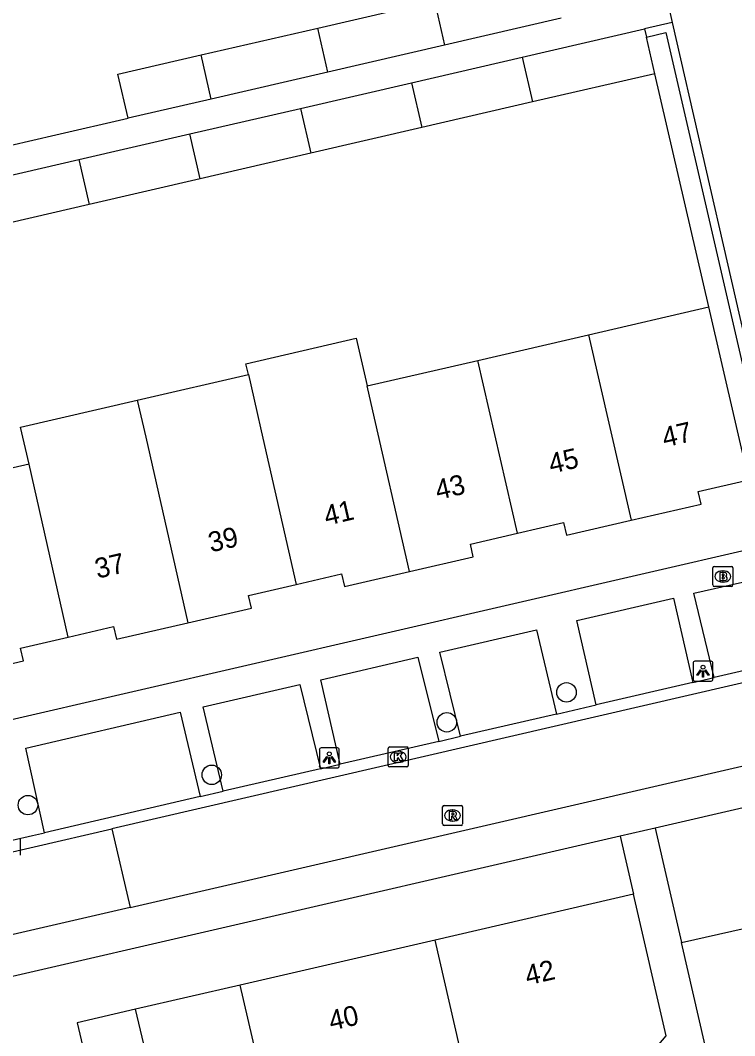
# Model space of a CAD drawing. Extents: x 156414 to 157775, y 382335 to 383765.
# Drawn here: x 156849.7 to 156885.5, y 382647.1 to 382698 of the extents above; entities that cross this region are included whole.
import ezdxf

# ---------------------------------------------------------------- set-up
doc = ezdxf.new("R2010")
doc.units = 0
for name, color, linetype in [('IMGEO_Boom', 7, 'Continuous'), ('IMGEO_Brandkraan', 7, 'Continuous'), ('IMGEO_Groenvoorziening', 7, 'Continuous'), ('IMGEO_Kolk', 7, 'Continuous'), ('IMGEO_Lichtpunt', 7, 'Continuous'), ('IMGEO_Muur', 7, 'Continuous'), ('IMGEO_Pand', 7, 'Continuous'), ('IMGEO_Pand_nummerreeks', 7, 'Continuous'), ('IMGEO_Rijbaan_lokaal_gesloten', 7, 'Continuous'), ('IMGEO_Rijbaan_lokaal_open', 7, 'Continuous'), ('IMGEO_Rioolput', 7, 'Continuous'), ('IMGEO_Voetpad_open', 7, 'Continuous')]:
    doc.layers.add(name, color=color, linetype=linetype)

msp = doc.modelspace()

# ---------------------------------------------------------------- linework, layer by layer
at = {"layer": 'IMGEO_Boom'}
for centre in [(156877.04, 382664.328), (156871.045, 382662.829), (156859.265, 382660.195), (156850.052, 382658.68)]:
    msp.add_circle(centre, 0.489, dxfattribs=at)
at = {"layer": 'IMGEO_Brandkraan'}
for p, q in [((156884.376, 382669.709), (156884.376, 382670.561)), ((156884.451, 382670.635), (156885.303, 382670.635)), ((156884.864, 382670.415), (156884.889, 382670.415)), ((156885.377, 382670.561), (156885.377, 382669.709)), ((156885.303, 382669.635), (156884.451, 382669.635)), ((156884.887, 382669.855), (156884.862, 382669.855))]:
    msp.add_line(p, q, dxfattribs=at)
for points in [[(156884.376, 382669.709), (156884.376, 382670.561)], [(156884.451, 382670.635), (156885.303, 382670.635)], [(156885.377, 382670.561), (156885.377, 382669.709)], [(156884.724, 382670.335), (156884.724, 382669.935), (156884.937, 382669.935)], [(156884.955, 382670.335), (156884.724, 382670.335)], [(156884.903, 382670.254), (156884.849, 382670.254), (156884.849, 382670.178)], [(156884.849, 382670.178), (156884.902, 382670.178)], [(156884.911, 382670.102), (156884.849, 382670.102), (156884.849, 382670.021)], [(156884.849, 382670.021), (156884.911, 382670.021)], [(156885.303, 382669.635), (156884.451, 382669.635)]]:
    msp.add_lwpolyline(points, dxfattribs=at)
for centre, radius, start, end in [((156884.453, 382670.559), 0.0765, 91.552, 178.448), ((156884.453, 382670.559), 0.0765, 91.552, 178.448), ((156885.301, 382670.559), 0.0765, 1.552, 88.448), ((156885.301, 382670.559), 0.0765, 1.552, 88.448), ((156884.904, 382670.216), 0.0379, 267.8285, 90.9355), ((156884.912, 382670.061), 0.0404, 269.8759, 90.5077), ((156884.943, 382670.186), 0.251, 268.6676, 293.5347), ((156884.959, 382670.19), 0.145, 59.4692, 91.5367), ((156884.984, 382670.237), 0.0922, 285.5137, 58.1501), ((156884.989, 382670.045), 0.105, 301.3115, 78.989), ((156884.453, 382669.711), 0.0765, 181.552, 268.448), ((156884.453, 382669.711), 0.0765, 181.552, 268.448), ((156885.301, 382669.711), 0.0765, 271.552, 358.448), ((156885.301, 382669.711), 0.0765, 271.552, 358.448)]:
    msp.add_arc(centre, radius, start, end, dxfattribs=at)
for centre, major_axis, ratio, start_param, end_param in [((156884.863, 382670.135), (-0.387, 0.002), 0.722429, 4.712389, 7.853982), ((156884.888, 382670.135), (-0.39, 0.002), 0.717154, 1.570796, 4.712389)]:
    msp.add_ellipse(centre, major_axis=major_axis, ratio=ratio, start_param=start_param, end_param=end_param, dxfattribs=at)
at = {"layer": 'IMGEO_Groenvoorziening'}
msp.add_lwpolyline([(156884.178, 382683.642), (156881.475, 382695.326)], dxfattribs=at)
at = {"layer": 'IMGEO_Kolk'}
for p, q in [((156868.106, 382660.67), (156868.106, 382661.522)), ((156868.181, 382661.596), (156869.033, 382661.596)), ((156868.594, 382661.376), (156868.619, 382661.376)), ((156869.107, 382661.522), (156869.107, 382660.67)), ((156868.617, 382660.816), (156868.592, 382660.816)), ((156869.033, 382660.596), (156868.181, 382660.596)), ((156849.67, 382657.017), (156849.67, 382656.165))]:
    msp.add_line(p, q, dxfattribs=at)
for points in [[(156868.106, 382660.67), (156868.106, 382661.522)], [(156868.181, 382661.596), (156869.033, 382661.596)], [(156868.427, 382661.296), (156868.55, 382661.296), (156868.55, 382661.145), (156868.68, 382661.296), (156868.844, 382661.296), (156868.698, 382661.145), (156868.851, 382660.896), (156868.699, 382660.896), (156868.614, 382661.06), (156868.55, 382660.993), (156868.55, 382660.896), (156868.427, 382660.896), (156868.427, 382661.296)], [(156869.107, 382661.522), (156869.107, 382660.67)], [(156869.033, 382660.596), (156868.181, 382660.596)], [(156849.67, 382657.017), (156849.67, 382656.165)]]:
    msp.add_lwpolyline(points, dxfattribs=at)
for centre, start, end in [((156868.183, 382661.52), 91.552, 178.448), ((156868.183, 382661.52), 91.552, 178.448), ((156869.031, 382661.52), 1.552, 88.448), ((156869.031, 382661.52), 1.552, 88.448), ((156868.183, 382660.672), 181.552, 268.448), ((156868.183, 382660.672), 181.552, 268.448), ((156869.031, 382660.672), 271.552, 358.448), ((156869.031, 382660.672), 271.552, 358.448)]:
    msp.add_arc(centre, 0.0765, start, end, dxfattribs=at)
for centre, major_axis, ratio, start_param, end_param in [((156868.593, 382661.096), (-0.387, 0.002), 0.722429, 4.712389, 7.853982), ((156868.618, 382661.096), (-0.39, 0.002), 0.717154, 1.570796, 4.712389)]:
    msp.add_ellipse(centre, major_axis=major_axis, ratio=ratio, start_param=start_param, end_param=end_param, dxfattribs=at)
at = {"layer": 'IMGEO_Lichtpunt'}
for p, q in [((156883.384, 382665.793), (156883.384, 382664.986)), ((156883.384, 382665.793), (156883.384, 382664.986)), ((156884.286, 382665.888), (156883.478, 382665.888)), ((156884.286, 382665.888), (156883.478, 382665.888)), ((156884.38, 382664.986), (156884.38, 382665.793)), ((156884.38, 382664.986), (156884.38, 382665.793)), ((156883.478, 382664.892), (156884.286, 382664.892)), ((156883.478, 382664.892), (156884.286, 382664.892)), ((156864.656, 382661.448), (156864.656, 382660.641)), ((156864.656, 382661.448), (156864.656, 382660.641)), ((156865.558, 382661.543), (156864.75, 382661.543)), ((156865.558, 382661.543), (156864.75, 382661.543)), ((156865.652, 382660.641), (156865.652, 382661.448)), ((156865.652, 382660.641), (156865.652, 382661.448)), ((156864.75, 382660.547), (156865.558, 382660.547)), ((156864.75, 382660.547), (156865.558, 382660.547))]:
    msp.add_line(p, q, dxfattribs=at)
for points in [[(156883.758, 382665.457), (156883.797, 382665.429), (156883.609, 382665.167), (156883.571, 382665.194), (156883.758, 382665.457)], [(156883.86, 382665.409), (156883.907, 382665.409), (156883.907, 382665.087), (156883.86, 382665.087), (156883.86, 382665.409)], [(156883.97, 382665.429), (156884.008, 382665.456), (156884.195, 382665.194), (156884.156, 382665.166), (156883.97, 382665.429)], [(156865.03, 382661.112), (156865.069, 382661.084), (156864.881, 382660.822), (156864.843, 382660.849), (156865.03, 382661.112)], [(156865.132, 382661.064), (156865.179, 382661.064), (156865.179, 382660.742), (156865.132, 382660.742), (156865.132, 382661.064)], [(156865.242, 382661.084), (156865.28, 382661.111), (156865.467, 382660.849), (156865.428, 382660.821), (156865.242, 382661.084)]]:
    msp.add_lwpolyline(points, dxfattribs=at)
for centre in [(156883.883, 382665.591), (156865.155, 382661.246)]:
    msp.add_circle(centre, 0.0994, dxfattribs=at)
for centre, start, end in [((156883.478, 382665.793), 90, 180), ((156883.478, 382665.793), 90, 180), ((156884.286, 382665.793), 0, 90), ((156884.286, 382665.793), 0, 90), ((156883.478, 382664.986), 180, 270), ((156883.478, 382664.986), 180, 270), ((156884.286, 382664.986), 270, 0), ((156884.286, 382664.986), 270, 360), ((156864.75, 382661.448), 90, 180), ((156864.75, 382661.448), 90, 180), ((156865.558, 382661.448), 0, 90), ((156865.558, 382661.448), 0, 90), ((156864.75, 382660.641), 180, 270), ((156864.75, 382660.641), 180, 270), ((156865.558, 382660.641), 270, 0), ((156865.558, 382660.641), 270, 360)]:
    msp.add_arc(centre, 0.0946, start, end, dxfattribs=at)
at = {"layer": 'IMGEO_Muur'}
for points in [[(156882.329, 382697.898), (156880.957, 382697.567)], [(156882.329, 382697.898), (156888.288, 382671.973)], [(156881.052, 382697.157), (156882.021, 382697.39), (156887.823, 382672.288), (156886.829, 382672.067)]]:
    msp.add_lwpolyline(points, dxfattribs=at)
at = {"layer": 'IMGEO_Pand'}
for points in [[(156864.577, 382697.612), (156870.42, 382698.958)], [(156870.42, 382698.958), (156870.926, 382696.756)], [(156876.769, 382698.106), (156870.926, 382696.756)], [(156858.734, 382696.267), (156864.577, 382697.612)], [(156865.085, 382695.406), (156864.577, 382697.612)], [(156874.825, 382696.153), (156880.957, 382697.567)], [(156880.957, 382697.567), (156881.052, 382697.157)], [(156881.475, 382695.326), (156881.052, 382697.157)], [(156870.926, 382696.756), (156865.085, 382695.406)], [(156855.07, 382693.093), (156854.56, 382695.305), (156858.734, 382696.267)], [(156859.242, 382694.056), (156858.734, 382696.267)], [(156869.281, 382694.874), (156874.825, 382696.153)], [(156874.825, 382696.153), (156875.341, 382693.909)], [(156865.085, 382695.406), (156859.242, 382694.056)], [(156881.475, 382695.326), (156875.341, 382693.909)], [(156863.714, 382693.59), (156869.281, 382694.874)], [(156869.281, 382694.874), (156869.797, 382692.629)], [(156859.242, 382694.056), (156855.07, 382693.093)], [(156875.341, 382693.909), (156869.797, 382692.629)], [(156858.167, 382692.311), (156863.714, 382693.59)], [(156863.714, 382693.59), (156864.233, 382691.343)], [(156852.602, 382691.028), (156858.167, 382692.311)], [(156858.691, 382690.063), (156858.167, 382692.311)], [(156869.797, 382692.629), (156864.233, 382691.343)], [(156864.233, 382691.343), (156858.691, 382690.063)], [(156846.758, 382689.68), (156852.602, 382691.028)], [(156852.602, 382691.028), (156853.127, 382688.778)], [(156858.691, 382690.063), (156853.127, 382688.778)], [(156853.127, 382688.778), (156847.281, 382687.428)], [(156878.14, 382682.246), (156884.178, 382683.642)], [(156886.175, 382674.984), (156884.178, 382683.642)], [(156861.099, 382680.255), (156860.976, 382680.795), (156866.498, 382682.072), (156867.045, 382679.681)], [(156872.596, 382680.964), (156878.14, 382682.246)], [(156878.14, 382682.246), (156880.278, 382672.952)], [(156867.045, 382679.681), (156872.596, 382680.964)], [(156874.579, 382672.302), (156872.596, 382680.964)], [(156855.53, 382678.968), (156855.737, 382679.016), (156861.099, 382680.255)], [(156861.099, 382680.255), (156861.522, 382678.404), (156861.743, 382677.439), (156863.502, 382669.739)], [(156869.171, 382670.383), (156867.247, 382678.796), (156867.045, 382679.681)], [(156850.107, 382675.766), (156849.677, 382677.616), (156855.53, 382678.968)], [(156855.53, 382678.968), (156855.961, 382677.118), (156858.064, 382667.813)], [(156850.107, 382675.766), (156849.902, 382675.718), (156848.627, 382675.424), (156844.253, 382674.413)], [(156852.075, 382667.095), (156850.107, 382675.766)], [(156880.278, 382672.952), (156883.788, 382673.764), (156883.642, 382674.398), (156886.175, 382674.984)], [(156874.579, 382672.302), (156876.891, 382672.837), (156877.037, 382672.202), (156880.278, 382672.952)], [(156869.171, 382670.383), (156872.37, 382671.123), (156872.224, 382671.757), (156874.579, 382672.302)], [(156863.502, 382669.739), (156865.765, 382670.263), (156865.911, 382669.628), (156869.171, 382670.383)], [(156858.064, 382667.813), (156861.254, 382668.551), (156861.108, 382669.185), (156863.502, 382669.739)], [(156852.075, 382667.095), (156854.346, 382667.621), (156854.492, 382666.987), (156858.064, 382667.813)], [(156846.373, 382665.108), (156849.825, 382665.907), (156849.679, 382666.541), (156852.075, 382667.095)], [(156880.396, 382654.211), (156870.453, 382651.916)], [(156878.231, 382642.629), (156882.031, 382647.125), (156880.396, 382654.211)], [(156882.804, 382651.789), (156886.514, 382652.638)], [(156870.453, 382651.916), (156860.696, 382649.664)], [(156871.916, 382645.58), (156870.453, 382651.916)], [(156883.984, 382646.633), (156882.804, 382651.789)], [(156860.696, 382649.664), (156855.435, 382648.45)], [(156862.379, 382643.377), (156862.159, 382643.326), (156860.696, 382649.664)], [(156855.435, 382648.45), (156852.515, 382647.776), (156853.2, 382644.857), (156850.275, 382644.18)], [(156858.38, 382636.696), (156858.242, 382636.664), (156855.435, 382648.45)]]:
    msp.add_lwpolyline(points, dxfattribs=at)
at = {"layer": 'IMGEO_Rijbaan_lokaal_gesloten'}
for points in [[(156921.083, 382672.955), (156894.488, 382666.782), (156889.852, 382665.724), (156854.261, 382657.483)], [(156855.169, 382653.553), (156921.11, 382668.783)], [(156743.958, 382632.023), (156745.677, 382632.413), (156818.765, 382649.282), (156850.364, 382656.581), (156854.261, 382657.483)], [(156854.261, 382657.483), (156855.169, 382653.553)], [(156855.169, 382653.553), (156819.996, 382645.43)]]:
    msp.add_lwpolyline(points, dxfattribs=at)
at = {"layer": 'IMGEO_Rijbaan_lokaal_open'}
for points in [[(156886.834, 382665.63), (156884.449, 382665.077)], [(156883.375, 382664.828), (156878.533, 382663.705)], [(156883.375, 382664.828), (156884.449, 382665.077)], [(156876.538, 382663.242), (156878.533, 382663.705)], [(156876.538, 382663.242), (156871.726, 382662.127)], [(156870.64, 382661.875), (156865.702, 382660.73)], [(156870.64, 382661.875), (156871.726, 382662.127)], [(156864.715, 382660.501), (156865.702, 382660.73)], [(156864.715, 382660.501), (156859.844, 382659.372)], [(156858.69, 382659.104), (156859.844, 382659.372)], [(156858.69, 382659.104), (156850.884, 382657.294)], [(156849.266, 382656.92), (156850.287, 382657.156), (156850.884, 382657.294)]]:
    msp.add_lwpolyline(points, dxfattribs=at)
at = {"layer": 'IMGEO_Rioolput'}
for p, q in [((156870.832, 382657.733), (156870.832, 382658.585)), ((156870.907, 382658.659), (156871.759, 382658.659)), ((156871.32, 382658.439), (156871.345, 382658.439)), ((156871.833, 382658.585), (156871.833, 382657.733)), ((156871.759, 382657.659), (156870.907, 382657.659)), ((156871.343, 382657.879), (156871.318, 382657.879))]:
    msp.add_line(p, q, dxfattribs=at)
for points in [[(156870.832, 382657.733), (156870.832, 382658.585)], [(156870.907, 382658.659), (156871.759, 382658.659)], [(156871.421, 382658.357), (156871.169, 382658.359), (156871.169, 382657.959)], [(156871.347, 382658.278), (156871.293, 382658.278), (156871.293, 382658.197)], [(156871.293, 382658.197), (156871.345, 382658.197)], [(156871.833, 382658.585), (156871.833, 382657.733)], [(156871.759, 382657.659), (156870.907, 382657.659)], [(156871.169, 382657.959), (156871.293, 382657.959), (156871.293, 382658.121), (156871.304, 382658.121)], [(156871.351, 382658.092), (156871.422, 382657.959), (156871.562, 382657.959), (156871.497, 382658.085)]]:
    msp.add_lwpolyline(points, dxfattribs=at)
for centre, radius, start, end in [((156870.909, 382658.583), 0.0765, 91.552, 178.448), ((156870.909, 382658.583), 0.0765, 91.552, 178.448), ((156871.329, 382658.386), 0.19, 274.7715, 282.9687), ((156871.353, 382658.182), 0.0964, 77.0061, 93.1865), ((156871.367, 382658.239), 0.0378, 276.6634, 79.6772), ((156871.42, 382658.247), 0.109, 350.3612, 89.416), ((156871.418, 382658.247), 0.112, 277.5842, 350.9817), ((156871.757, 382658.583), 0.0765, 1.552, 88.448), ((156871.757, 382658.583), 0.0765, 1.552, 88.448), ((156870.909, 382657.735), 0.0765, 181.552, 268.448), ((156870.909, 382657.735), 0.0765, 181.552, 268.448), ((156871.303, 382658.068), 0.0533, 26.0293, 88.6989), ((156871.402, 382658.032), 0.108, 29.5134, 73.7905), ((156871.757, 382657.735), 0.0765, 271.552, 358.448), ((156871.757, 382657.735), 0.0765, 271.552, 358.448)]:
    msp.add_arc(centre, radius, start, end, dxfattribs=at)
for centre, major_axis, ratio, start_param, end_param in [((156871.319, 382658.159), (-0.387, 0.002), 0.722429, 4.712389, 7.853982), ((156871.344, 382658.159), (-0.39, 0.002), 0.717154, 1.570796, 4.712389)]:
    msp.add_ellipse(centre, major_axis=major_axis, ratio=ratio, start_param=start_param, end_param=end_param, dxfattribs=at)
at = {"layer": 'IMGEO_Voetpad_open'}
for points in [[(156882.027, 382699.321), (156882.329, 382697.898)], [(156847.98, 382691.455), (156851.452, 382692.257), (156855.07, 382693.093)], [(156886.92, 382671.657), (156848.729, 382662.829), (156818.728, 382655.884)], [(156884.449, 382665.077), (156883.426, 382669.292), (156885.853, 382669.854), (156886.834, 382665.63)], [(156878.533, 382663.705), (156877.552, 382667.932), (156882.397, 382669.054), (156883.375, 382664.828)], [(156871.726, 382662.127), (156870.701, 382666.345), (156875.546, 382667.467), (156876.538, 382663.242)], [(156921.541, 382666.777), (156881.479, 382657.529)], [(156865.702, 382660.73), (156864.724, 382664.961), (156869.595, 382666.089), (156870.64, 382661.875)], [(156859.844, 382659.372), (156858.832, 382663.596), (156863.676, 382664.718), (156864.715, 382660.501)], [(156850.884, 382657.294), (156849.944, 382661.538), (156857.688, 382663.331), (156858.69, 382659.104)], [(156881.479, 382657.529), (156879.724, 382657.124)], [(156881.479, 382657.529), (156882.804, 382651.789)], [(156879.724, 382657.124), (156821.844, 382643.764)], [(156879.724, 382657.124), (156880.396, 382654.211)]]:
    msp.add_lwpolyline(points, dxfattribs=at)

# ---------------------------------------------------------------- texts
at = {"layer": 'IMGEO_Pand_nummerreeks'}
for s, rotation, p in [('47', 13.0248, (156881.959, 382676.596)), ('45', 13.0248, (156876.274, 382675.281)), ('43', 13.0233, (156870.59, 382673.966)), ('41', 13.0233, (156865.015, 382672.676)), ('39', 13.0233, (156859.22, 382671.336)), ('37', 13.0248, (156853.536, 382670.021)), ('42', 13.0004, (156875.091, 382649.642)), ('40', 13.0061, (156865.255, 382647.37))]:
    msp.add_text(s, height=1, rotation=rotation, dxfattribs=at).set_placement(p)

doc.saveas('drawing.dxf')
